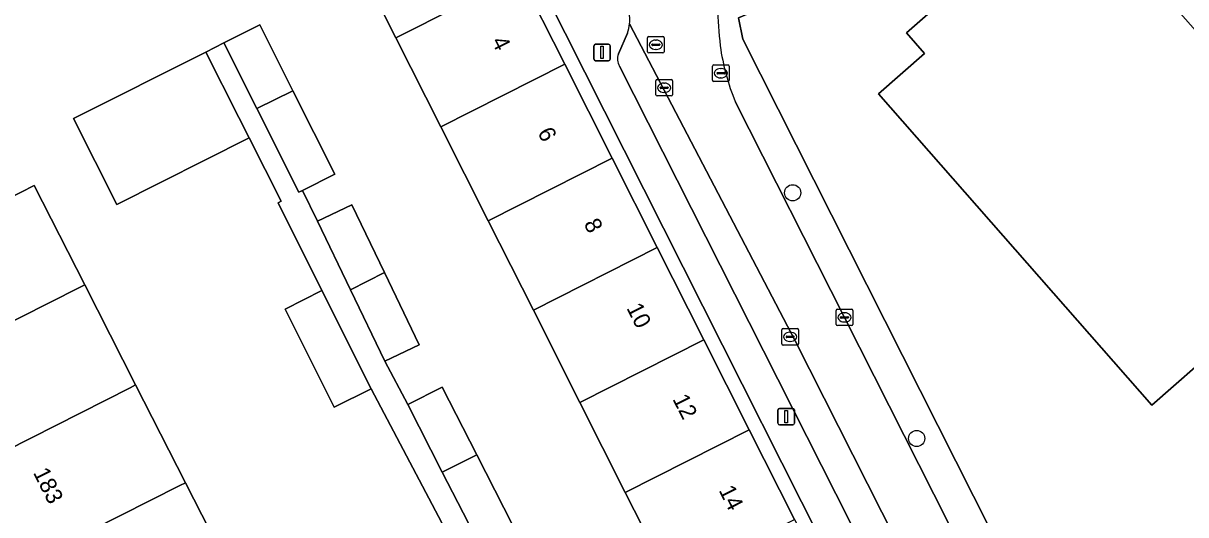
# Model space of a CAD drawing. Extents: x 162344 to 162869, y 381217 to 381818.
# Drawn here: x 162388.7 to 162459.1, y 381624.8 to 381654.6 of the extents above; entities that cross this region are included whole.
import ezdxf

# ---------------------------------------------------------------- set-up
doc = ezdxf.new("R2010")
doc.units = 0
for name, color, linetype in [('IMGEO_Boom', 7, 'Continuous'), ('IMGEO_Erf', 7, 'Continuous'), ('IMGEO_Kolk', 7, 'Continuous'), ('IMGEO_Lichtmast', 7, 'Continuous'), ('IMGEO_Pand', 7, 'Continuous'), ('IMGEO_Pand_nummerreeks', 7, 'Continuous'), ('IMGEO_Parkeervlak_open', 7, 'Continuous'), ('IMGEO_Rijbaan_lokaal_open', 7, 'Continuous'), ('IMGEO_Rioolput', 7, 'Continuous'), ('IMGEO_Voetpad_open', 7, 'Continuous')]:
    doc.layers.add(name, color=color, linetype=linetype)

msp = doc.modelspace()

# ---------------------------------------------------------------- linework, layer by layer
at = {"layer": 'IMGEO_Boom'}
for centre in [(162435.249, 381644.33), (162442.757, 381629.448)]:
    msp.add_circle(centre, 0.489, dxfattribs=at)
at = {"layer": 'IMGEO_Erf'}
for points in [[(162481.795, 381631.988), (162472.56, 381646.493), (162471.067, 381648.837), (162460.935, 381661.289), (162452.016, 381672.565), (162451.197, 381672.343), (162448.302, 381667.139), (162445.27, 381668.731), (162442.545, 381663.577), (162439.544, 381661.021), (162435.222, 381659.331), (162436.115, 381656.689), (162431.972, 381654.923), (162432.233, 381653.635), (162452.631, 381613.197), (162453.177, 381613.49), (162453.166, 381613.535), (162453.909, 381613.922), (162459.405, 381616.959), (162465.658, 381620.415), (162465.1, 381621.456)], [(162416.703, 381663.475), (162415.849, 381663.025), (162415.866, 381662.989), (162415.867, 381662.99), (162415.945, 381663.03), (162418.73, 381657.511), (162421.45, 381652.12), (162424.321, 381646.43), (162427.054, 381641.014), (162429.874, 381635.425), (162432.623, 381629.979), (162435.371, 381624.533), (162436.297, 381622.697), (162438.213, 381618.9), (162440.946, 381613.483), (162443.722, 381607.981), (162446.477, 381602.521), (162449.333, 381596.861), (162452.128, 381591.331), (162454.951, 381585.737), (162455.733, 381586.132), (162450.084, 381597.259)], [(162457.002, 381631.47), (162440.439, 381650.319), (162443.233, 381652.774), (162442.142, 381654.015), (162449.248, 381660.259), (162450.273, 381659.093), (162453.049, 381661.533), (162455.031, 381659.277), (162457.216, 381661.198), (162459.336, 381658.786), (162457.226, 381656.932), (162467.795, 381644.904), (162466.539, 381643.799), (162467.852, 381642.305), (162469.109, 381643.41), (162472.178, 381639.917), (162463.598, 381632.222), (162461.097, 381635.067)]]:
    msp.add_lwpolyline(points, close=True, dxfattribs=at)
for points in [[(162427.866, 381620.735), (162425.117, 381626.182), (162422.369, 381631.627), (162419.549, 381637.215), (162416.815, 381642.631), (162413.943, 381648.322), (162411.223, 381653.711), (162408.443, 381659.219)], [(162409.724, 381632.464), (162407.493, 381631.334), (162404.519, 381637.283), (162406.749, 381638.413), (162404.093, 381643.724), (162404.281, 381643.819), (162402.34, 381647.657), (162394.326, 381643.627), (162391.711, 381648.827), (162399.713, 381652.851), (162400.813, 381653.404), (162402.978, 381654.492), (162404.977, 381650.514), (162407.524, 381645.45), (162405.563, 381644.464), (162406.484, 381642.6), (162408.559, 381643.596), (162410.531, 381639.492), (162412.63, 381635.122), (162410.555, 381634.126), (162411.946, 381631.498), (162414.024, 381632.562), (162416.12, 381628.465), (162418.317, 381624.171)], [(162383.789, 381641.951), (162389.324, 381644.767), (162392.382, 381638.757), (162395.465, 381632.697), (162398.481, 381626.77), (162401.468, 381620.899), (162404.512, 381614.916), (162398.902, 381612.062), (162394.445, 381609.794), (162393.56, 381611.534), (162393.333, 381611.419), (162391.947, 381614.144), (162392.214, 381614.28), (162391.431, 381615.821), (162392.072, 381616.147), (162391.598, 381617.079), (162391.087, 381617.106), (162390.098, 381619.05), (162390.426, 381619.555), (162389.157, 381622.048), (162388.7, 381622.947), (162388.095, 381622.98)], [(162417.121, 381618.435), (162409.724, 381632.464)]]:
    msp.add_lwpolyline(points, dxfattribs=at)
at = {"layer": 'IMGEO_Kolk'}
for p, q in [((162430.399, 381651.144), (162430.399, 381651.996)), ((162430.474, 381652.07), (162431.326, 381652.07)), ((162430.658, 381651.564), (162430.658, 381651.576)), ((162431.096, 381651.527), (162430.698, 381651.527)), ((162430.701, 381651.613), (162431.099, 381651.613)), ((162430.887, 381651.85), (162430.912, 381651.85)), ((162431.142, 381651.576), (162431.142, 381651.564)), ((162431.4, 381651.996), (162431.4, 381651.144)), ((162426.969, 381650.266), (162426.969, 381651.118)), ((162427.044, 381651.192), (162427.896, 381651.192)), ((162427.457, 381650.972), (162427.482, 381650.972)), ((162427.97, 381651.118), (162427.97, 381650.266)), ((162431.326, 381651.07), (162430.474, 381651.07)), ((162430.91, 381651.29), (162430.885, 381651.29)), ((162427.896, 381650.192), (162427.044, 381650.192)), ((162427.228, 381650.686), (162427.228, 381650.698)), ((162427.666, 381650.649), (162427.268, 381650.649)), ((162427.271, 381650.735), (162427.669, 381650.735)), ((162427.48, 381650.412), (162427.455, 381650.412)), ((162427.712, 381650.698), (162427.712, 381650.686)), ((162437.885, 381636.356), (162437.885, 381637.208)), ((162437.96, 381637.282), (162438.812, 381637.282)), ((162438.144, 381636.776), (162438.144, 381636.788)), ((162438.582, 381636.739), (162438.184, 381636.739)), ((162438.187, 381636.825), (162438.585, 381636.825)), ((162438.373, 381637.062), (162438.398, 381637.062)), ((162438.628, 381636.788), (162438.628, 381636.776)), ((162438.886, 381637.208), (162438.886, 381636.356)), ((162434.595, 381635.179), (162434.595, 381636.031)), ((162434.67, 381636.105), (162435.522, 381636.105)), ((162435.596, 381636.031), (162435.596, 381635.179)), ((162438.812, 381636.282), (162437.96, 381636.282)), ((162438.396, 381636.502), (162438.371, 381636.502)), ((162434.854, 381635.599), (162434.854, 381635.611)), ((162435.292, 381635.562), (162434.894, 381635.562)), ((162434.897, 381635.648), (162435.295, 381635.648)), ((162435.106, 381635.325), (162435.081, 381635.325)), ((162435.083, 381635.885), (162435.108, 381635.885)), ((162435.338, 381635.611), (162435.338, 381635.599)), ((162435.522, 381635.105), (162434.67, 381635.105))]:
    msp.add_line(p, q, dxfattribs=at)
for points in [[(162430.399, 381651.144), (162430.399, 381651.996)], [(162430.474, 381652.07), (162431.326, 381652.07)], [(162431.4, 381651.996), (162431.4, 381651.144)], [(162426.969, 381650.266), (162426.969, 381651.118)], [(162427.044, 381651.192), (162427.896, 381651.192)], [(162427.97, 381651.118), (162427.97, 381650.266)], [(162431.326, 381651.07), (162430.474, 381651.07)], [(162427.896, 381650.192), (162427.044, 381650.192)], [(162437.885, 381636.356), (162437.885, 381637.208)], [(162437.96, 381637.282), (162438.812, 381637.282)], [(162438.886, 381637.208), (162438.886, 381636.356)], [(162434.595, 381635.179), (162434.595, 381636.031)], [(162434.67, 381636.105), (162435.522, 381636.105)], [(162435.596, 381636.031), (162435.596, 381635.179)], [(162438.812, 381636.282), (162437.96, 381636.282)], [(162435.522, 381635.105), (162434.67, 381635.105)]]:
    msp.add_lwpolyline(points, dxfattribs=at)
for centre, radius, start, end in [((162430.476, 381651.994), 0.0765, 91.55205, 178.44795), ((162430.476, 381651.994), 0.0765, 91.55205, 178.44795), ((162430.698, 381651.573), 0.0403, 85.87752, 175.75265), ((162430.695, 381651.563), 0.0366, 178.93798, 274.71019), ((162431.099, 381651.57), 0.043, 264.86636, 352.45326), ((162431.103, 381651.575), 0.0386, 1.73085, 96.63898), ((162431.324, 381651.994), 0.0765, 1.55205, 88.44795), ((162431.324, 381651.994), 0.0765, 1.55205, 88.44795), ((162427.046, 381651.116), 0.0765, 91.55205, 178.44795), ((162427.046, 381651.116), 0.0765, 91.55205, 178.44795), ((162427.894, 381651.116), 0.0765, 1.55205, 88.44795), ((162427.894, 381651.116), 0.0765, 1.55205, 88.44795), ((162430.476, 381651.146), 0.0765, 181.55205, 268.44795), ((162430.476, 381651.146), 0.0765, 181.55205, 268.44795), ((162431.324, 381651.146), 0.0765, 271.55205, 358.44795), ((162431.324, 381651.146), 0.0765, 271.55205, 358.44795), ((162427.046, 381650.268), 0.0765, 181.55205, 268.44795), ((162427.046, 381650.268), 0.0765, 181.55205, 268.44795), ((162427.268, 381650.695), 0.0403, 85.87752, 175.75265), ((162427.265, 381650.685), 0.0366, 178.93798, 274.71019), ((162427.669, 381650.692), 0.043, 264.86636, 352.45326), ((162427.673, 381650.697), 0.0386, 1.73085, 96.63898), ((162427.894, 381650.268), 0.0765, 271.55205, 358.44795), ((162427.894, 381650.268), 0.0765, 271.55205, 358.44795), ((162437.962, 381637.206), 0.0765, 91.55205, 178.44795), ((162437.962, 381637.206), 0.0765, 91.55205, 178.44795), ((162438.184, 381636.785), 0.0403, 85.87752, 175.75265), ((162438.181, 381636.775), 0.0366, 178.93798, 274.71019), ((162438.585, 381636.782), 0.043, 264.86636, 352.45326), ((162438.589, 381636.787), 0.0386, 1.73085, 96.63898), ((162438.81, 381637.206), 0.0765, 1.55205, 88.44795), ((162438.81, 381637.206), 0.0765, 1.55205, 88.44795), ((162434.672, 381636.029), 0.0765, 91.55205, 178.44795), ((162434.672, 381636.029), 0.0765, 91.55205, 178.44795), ((162435.52, 381636.029), 0.0765, 1.55205, 88.44795), ((162435.52, 381636.029), 0.0765, 1.55205, 88.44795), ((162437.962, 381636.358), 0.0765, 181.55205, 268.44795), ((162437.962, 381636.358), 0.0765, 181.55205, 268.44795), ((162438.81, 381636.358), 0.0765, 271.55205, 358.44795), ((162438.81, 381636.358), 0.0765, 271.55205, 358.44795), ((162434.894, 381635.608), 0.0403, 85.87752, 175.75265), ((162434.891, 381635.598), 0.0366, 178.93798, 274.71019), ((162435.295, 381635.605), 0.043, 264.86636, 352.45326), ((162435.299, 381635.61), 0.0386, 1.73085, 96.63898), ((162434.672, 381635.181), 0.0765, 181.55205, 268.44795), ((162434.672, 381635.181), 0.0765, 181.55205, 268.44795), ((162435.52, 381635.181), 0.0765, 271.55205, 358.44795), ((162435.52, 381635.181), 0.0765, 271.55205, 358.44795)]:
    msp.add_arc(centre, radius, start, end, dxfattribs=at)
for centre, major_axis, ratio, start_param, end_param in [((162430.886, 381651.57), (-0.387, 0.002), 0.722429, 4.712389, 7.853982), ((162430.911, 381651.57), (-0.39, 0.002), 0.717154, 1.570796, 4.712389), ((162427.456, 381650.692), (-0.387, 0.002), 0.722429, 4.712389, 7.853982), ((162427.481, 381650.692), (-0.39, 0.002), 0.717154, 1.570796, 4.712389), ((162438.372, 381636.782), (-0.387, 0.002), 0.722429, 4.712389, 7.853982), ((162438.397, 381636.782), (-0.39, 0.002), 0.717154, 1.570796, 4.712389), ((162435.082, 381635.605), (-0.387, 0.002), 0.722429, 4.712389, 7.853982), ((162435.107, 381635.605), (-0.39, 0.002), 0.717154, 1.570796, 4.712389)]:
    msp.add_ellipse(centre, major_axis=major_axis, ratio=ratio, start_param=start_param, end_param=end_param, dxfattribs=at)
at = {"layer": 'IMGEO_Lichtmast'}
for p, q in [((162423.214, 381652.429), (162423.214, 381653.229)), ((162423.214, 381653.229), (162423.214, 381652.429)), ((162423.314, 381653.329), (162424.104, 381653.329)), ((162424.104, 381653.329), (162423.314, 381653.329)), ((162424.204, 381653.229), (162424.204, 381652.429)), ((162424.204, 381652.429), (162424.204, 381653.229)), ((162424.104, 381652.329), (162423.314, 381652.329)), ((162423.314, 381652.329), (162424.104, 381652.329)), ((162434.362, 381630.373), (162434.362, 381631.173)), ((162434.362, 381631.173), (162434.362, 381630.373)), ((162434.462, 381631.273), (162435.252, 381631.273)), ((162435.252, 381631.273), (162434.462, 381631.273)), ((162435.352, 381631.173), (162435.352, 381630.373)), ((162435.352, 381630.373), (162435.352, 381631.173)), ((162435.252, 381630.273), (162434.462, 381630.273)), ((162434.462, 381630.273), (162435.252, 381630.273))]:
    msp.add_line(p, q, dxfattribs=at)
for points in [[(162423.634, 381653.204), (162423.784, 381653.204), (162423.784, 381652.454), (162423.634, 381652.454), (162423.634, 381653.204)], [(162434.782, 381631.148), (162434.932, 381631.148), (162434.932, 381630.398), (162434.782, 381630.398), (162434.782, 381631.148)]]:
    msp.add_lwpolyline(points, dxfattribs=at)
for centre, start, end in [((162423.314, 381653.229), 90, 180), ((162423.314, 381653.229), 90, 180), ((162424.104, 381653.229), 0, 90), ((162424.104, 381653.229), 360, 90), ((162423.314, 381652.429), 180, 270), ((162423.314, 381652.429), 180, 270), ((162424.104, 381652.429), 270, 0), ((162424.104, 381652.429), 270, 0), ((162434.462, 381631.173), 90, 180), ((162434.462, 381631.173), 90, 180), ((162435.252, 381631.173), 0, 90), ((162435.252, 381631.173), 360, 90), ((162434.462, 381630.373), 180, 270), ((162434.462, 381630.373), 180, 270), ((162435.252, 381630.373), 270, 0), ((162435.252, 381630.373), 270, 0)]:
    msp.add_arc(centre, 0.1, start, end, dxfattribs=at)
at = {"layer": 'IMGEO_Pand'}
for points in [[(162415.945, 381663.03), (162415.867, 381662.99), (162415.866, 381662.989), (162408.443, 381659.219), (162411.223, 381653.711), (162418.73, 381657.511)], [(162461.097, 381635.067), (162463.598, 381632.222), (162472.178, 381639.917), (162469.109, 381643.41), (162467.852, 381642.305), (162466.539, 381643.799), (162467.795, 381644.904), (162457.226, 381656.932), (162459.336, 381658.786), (162457.216, 381661.198), (162455.031, 381659.277), (162453.049, 381661.533), (162450.273, 381659.093), (162449.248, 381660.259), (162442.142, 381654.015), (162443.233, 381652.774), (162440.439, 381650.319), (162457.002, 381631.47)], [(162418.73, 381657.511), (162411.223, 381653.711), (162413.943, 381648.322), (162421.45, 381652.12)], [(162400.813, 381653.404), (162402.812, 381649.427), (162404.977, 381650.514), (162402.978, 381654.492)], [(162402.34, 381647.657), (162401.722, 381648.879), (162399.713, 381652.851), (162391.711, 381648.827), (162394.326, 381643.627)], [(162421.45, 381652.12), (162413.943, 381648.322), (162416.815, 381642.631), (162424.321, 381646.43)], [(162404.977, 381650.514), (162402.812, 381649.427), (162405.359, 381644.361), (162405.563, 381644.464), (162407.524, 381645.45)], [(162424.321, 381646.43), (162416.815, 381642.631), (162419.549, 381637.215), (162427.054, 381641.014)], [(162383.063, 381634.048), (162392.066, 381638.601), (162392.382, 381638.757), (162389.324, 381644.767), (162383.789, 381641.951), (162379.332, 381639.684), (162380.199, 381637.98), (162379.965, 381637.861), (162381.993, 381633.874), (162382.175, 381633.967), (162382.323, 381633.676)], [(162406.484, 381642.6), (162408.473, 381638.458), (162410.531, 381639.492), (162408.559, 381643.596)], [(162427.054, 381641.014), (162419.549, 381637.215), (162422.369, 381631.627), (162429.874, 381635.425)], [(162410.531, 381639.492), (162408.473, 381638.458), (162410.555, 381634.126), (162412.63, 381635.122)], [(162383.063, 381634.048), (162384.46, 381631.302), (162384.164, 381630.847), (162385.199, 381628.813), (162385.688, 381628.787), (162386.11, 381627.958), (162395.139, 381632.524), (162395.465, 381632.697), (162392.382, 381638.757), (162392.066, 381638.601)], [(162406.749, 381638.413), (162404.519, 381637.283), (162407.493, 381631.334), (162409.724, 381632.464)], [(162429.874, 381635.425), (162422.369, 381631.627), (162425.117, 381626.182), (162432.623, 381629.979)], [(162389.157, 381622.048), (162398.14, 381626.591), (162398.481, 381626.77), (162395.465, 381632.697), (162395.139, 381632.524), (162386.11, 381627.958), (162387.426, 381625.372), (162387.118, 381624.899), (162388.095, 381622.98), (162388.7, 381622.947)], [(162411.946, 381631.498), (162414.037, 381627.411), (162416.12, 381628.465), (162414.024, 381632.562)], [(162432.623, 381629.979), (162425.117, 381626.182), (162427.866, 381620.735), (162435.371, 381624.533)], [(162416.12, 381628.465), (162414.037, 381627.411), (162416.239, 381623.108), (162416.38, 381623.18), (162418.317, 381624.171)], [(162398.481, 381626.77), (162398.14, 381626.591), (162389.157, 381622.048), (162390.426, 381619.555), (162390.098, 381619.05), (162391.087, 381617.106), (162391.598, 381617.079), (162392.072, 381616.147), (162401.111, 381620.715), (162401.468, 381620.899)]]:
    msp.add_lwpolyline(points, close=True, dxfattribs=at)
at = {"layer": 'IMGEO_Parkeervlak_open'}
for points in [[(162491.571, 381524.186), (162460.5, 381585.739), (162459.315, 381588.084), (162459.045, 381588.618), (162435.395, 381635.369), (162425.373, 381654.562)], [(162425.245, 381654.004), (162424.695, 381652.736)], [(162424.757, 381651.992), (162433.476, 381634.757), (162458.021, 381586.227), (162484.409, 381533.947), (162488.481, 381525.898)]]:
    msp.add_lwpolyline(points, dxfattribs=at)
for centre, radius, start, end in [((162422.895, 381654.837), 2.493, 340.4866, 353.67419), ((162425.604, 381652.437), 0.957, 161.79383, 207.73345)]:
    msp.add_arc(centre, radius, start, end, dxfattribs=at)
at = {"layer": 'IMGEO_Rijbaan_lokaal_open'}
msp.add_lwpolyline([(162425.373, 381654.562), (162435.395, 381635.369), (162459.045, 381588.618), (162459.315, 381588.084), (162462.238, 381589.534), (162454.794, 381604.194), (162446.504, 381620.717), (162438.386, 381636.782), (162431.784, 381649.823)], dxfattribs=at)
for centre, radius, start, end in [((162458.629, 381656.353), 27.94, 176.74545, 186.41724), ((162422.893, 381654.833), 2.494, 353.76798, 16.66279), ((162444.727, 381655.146), 13.995, 187.86818, 202.35442)]:
    msp.add_arc(centre, radius, start, end, dxfattribs=at)
at = {"layer": 'IMGEO_Rioolput'}
for p, q in [((162426.466, 381652.87), (162426.466, 381653.722)), ((162426.541, 381653.796), (162427.393, 381653.796)), ((162427.467, 381653.722), (162427.467, 381652.87)), ((162426.725, 381653.29), (162426.725, 381653.302)), ((162427.163, 381653.253), (162426.765, 381653.253)), ((162426.768, 381653.339), (162427.166, 381653.339)), ((162426.977, 381653.016), (162426.952, 381653.016)), ((162426.954, 381653.576), (162426.979, 381653.576)), ((162427.209, 381653.302), (162427.209, 381653.29)), ((162427.393, 381652.796), (162426.541, 381652.796))]:
    msp.add_line(p, q, dxfattribs=at)
for points in [[(162426.466, 381652.87), (162426.466, 381653.722)], [(162426.541, 381653.796), (162427.393, 381653.796)], [(162427.467, 381653.722), (162427.467, 381652.87)], [(162427.393, 381652.796), (162426.541, 381652.796)]]:
    msp.add_lwpolyline(points, dxfattribs=at)
for centre, radius, start, end in [((162426.543, 381653.72), 0.0765, 91.55205, 178.44795), ((162426.543, 381653.72), 0.0765, 91.55205, 178.44795), ((162427.391, 381653.72), 0.0765, 1.55205, 88.44795), ((162427.391, 381653.72), 0.0765, 1.55205, 88.44795), ((162426.765, 381653.299), 0.0403, 85.87752, 175.75265), ((162426.762, 381653.289), 0.0366, 178.93798, 274.71019), ((162427.166, 381653.296), 0.043, 264.86636, 352.45326), ((162427.17, 381653.301), 0.0386, 1.73085, 96.63898), ((162426.543, 381652.872), 0.0765, 181.55205, 268.44795), ((162426.543, 381652.872), 0.0765, 181.55205, 268.44795), ((162427.391, 381652.872), 0.0765, 271.55205, 358.44795), ((162427.391, 381652.872), 0.0765, 271.55205, 358.44795)]:
    msp.add_arc(centre, radius, start, end, dxfattribs=at)
for centre, major_axis, ratio, start_param, end_param in [((162426.953, 381653.296), (-0.387, 0.002), 0.722429, 4.712389, 7.853982), ((162426.978, 381653.296), (-0.39, 0.002), 0.717154, 1.570796, 4.712389)]:
    msp.add_ellipse(centre, major_axis=major_axis, ratio=ratio, start_param=start_param, end_param=end_param, dxfattribs=at)
at = {"layer": 'IMGEO_Voetpad_open'}
for points in [[(162430.818, 381673.015), (162428.569, 381675.765), (162428.211, 381675.44), (162428.12, 381675.14), (162427.72, 381671.816), (162428.169, 381670.985), (162415.217, 381664.354), (162415.849, 381663.025), (162416.703, 381663.475), (162450.084, 381597.259), (162455.733, 381586.132), (162456.714, 381584.2), (162490.31, 381518.027), (162489.593, 381517.672), (162491.115, 381514.642), (162508.217, 381521.986), (162531.132, 381531.827), (162531.201, 381531.856), (162536.299, 381534.045), (162538.625, 381535.045), (162540.608, 381535.896), (162537.512, 381541.598)], [(162459.405, 381616.959), (162453.909, 381613.922), (162453.166, 381613.535), (162453.177, 381613.49), (162452.631, 381613.197), (162432.233, 381653.635), (162431.972, 381654.923), (162436.115, 381656.689), (162435.222, 381659.331), (162439.544, 381661.021), (162442.545, 381663.577), (162445.27, 381668.731), (162448.302, 381667.139), (162451.197, 381672.343), (162452.016, 381672.565), (162453.433, 381673.852), (162452.665, 381674.774)], [(162424.695, 381652.736), (162425.245, 381654.004)], [(162416.239, 381623.108), (162414.037, 381627.411), (162411.946, 381631.498), (162410.555, 381634.126), (162408.473, 381638.458), (162406.484, 381642.6), (162405.563, 381644.464), (162405.359, 381644.361), (162402.812, 381649.427), (162400.813, 381653.404), (162399.713, 381652.851), (162401.722, 381648.879), (162402.34, 381647.657), (162404.281, 381643.819), (162404.093, 381643.724), (162406.749, 381638.413), (162409.724, 381632.464), (162417.121, 381618.435)], [(162488.481, 381525.898), (162484.409, 381533.947), (162458.021, 381586.227), (162433.476, 381634.757), (162424.757, 381651.992)], [(162431.784, 381649.823), (162438.386, 381636.782), (162446.504, 381620.717), (162454.794, 381604.194), (162462.238, 381589.534), (162463.431, 381587.185), (162464.059, 381585.948), (162471.49, 381571.265), (162480.304, 381553.954), (162489.2, 381536.187)]]:
    msp.add_lwpolyline(points, dxfattribs=at)
for centre, radius, start, end in [((162458.629, 381656.353), 27.94, 176.74545, 186.41724), ((162422.893, 381654.833), 2.494, 353.76798, 16.66279), ((162422.895, 381654.837), 2.493, 340.4866, 353.67419), ((162444.727, 381655.146), 13.995, 187.86818, 202.35442), ((162425.604, 381652.437), 0.957, 161.79383, 207.73345)]:
    msp.add_arc(centre, radius, start, end, dxfattribs=at)

# ---------------------------------------------------------------- texts
at = {"layer": 'IMGEO_Pand_nummerreeks'}
for s, rotation, p in [('4', 296.84286, (162416.989, 381653.508)), ('6', 296.84286, (162419.783, 381647.987)), ('8', 296.84286, (162422.579, 381642.461)), ('10', 296.84286, (162425.167, 381637.351)), ('12', 296.84286, (162427.958, 381631.835)), ('183', 296.71461, (162389.239, 381627.382)), ('14', 296.84286, (162430.754, 381626.311))]:
    msp.add_text(s, height=1, rotation=rotation, dxfattribs=at).set_placement(p)

doc.saveas('drawing.dxf')
